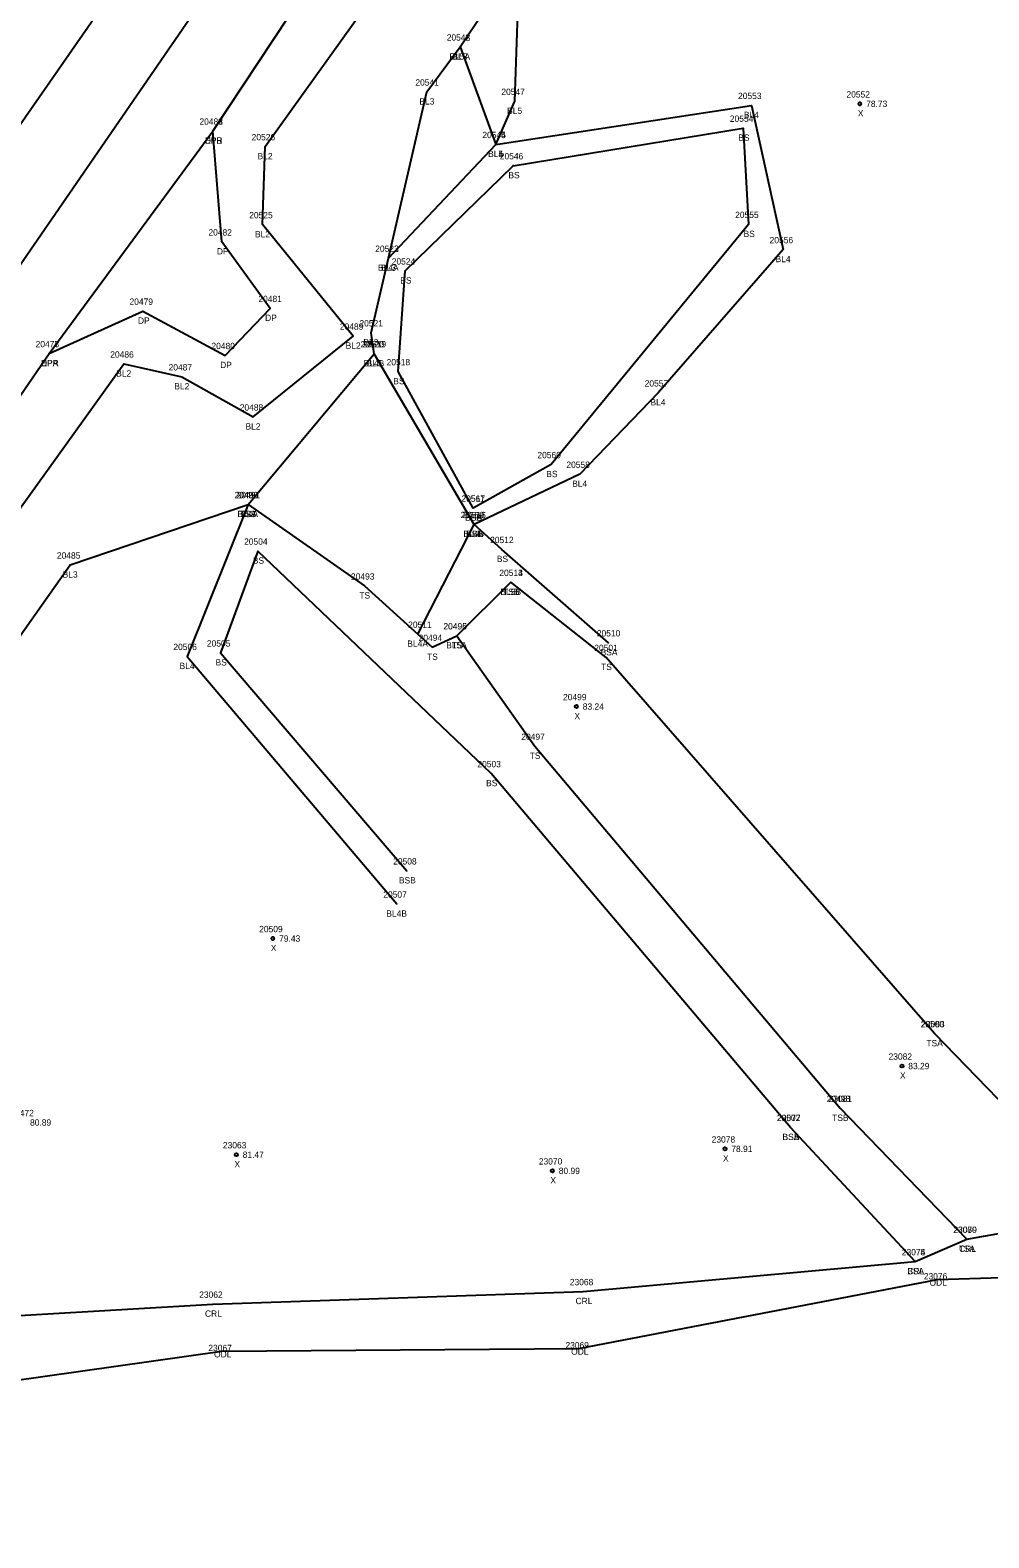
# Model space of a CAD drawing. Extents: x 2266664 to 2272385, y 716533 to 724777.
# Drawn here: x 2267788 to 2267939.8, y 717913.4 to 718152.1 of the extents above; entities that cross this region are included whole.
import ezdxf

# ---------------------------------------------------------------- set-up
doc = ezdxf.new("R2010")
doc.units = 0
for name, color, linetype in [('RD_DTM_BkLn1', 7, 'Continuous'), ('RD_DTM_BkLn2', 7, 'Continuous'), ('RD_EX_Driveway', 7, 'Continuous'), ('RD_EX_Driveway_txCode', 7, 'Continuous'), ('RD_EX_H2O', 7, 'Continuous'), ('RD_EX_H2O_txCode', 7, 'Continuous'), ('RD_EX_Road', 7, 'Continuous'), ('RD_EX_Road_txCode', 7, 'Continuous'), ('RD_Sketch8', 7, 'Continuous'), ('RD_SMD_Locator', 7, 'Continuous'), ('RD_SMD_Misc', 7, 'Continuous')]:
    doc.layers.add(name, color=color, linetype=linetype)

msp = doc.modelspace()

# ---------------------------------------------------------------- linework, layer by layer
at = {"layer": 'RD_DTM_BkLn1'}
msp.add_line((2267855.58, 718056.22), (2267864.15, 718064.68), dxfattribs=at)
for points in [[(2267710.19, 717938.44), (2267719.21, 717959.32), (2267751.93, 718007.38), (2267794.35, 718067.43), (2267822.53, 718077), (2267842.49, 718100.88), (2267841.99, 718104.19), (2267844.77, 718116), (2267850.84, 718142.33), (2267856.09, 718149.45), (2267873.81, 718175.89), (2267927.8, 718259.2), (2267986.43, 718342), (2268046.41, 718424.35), (2268102.94, 718500.87), (2268161.82, 718580.38), (2268222.22, 718658.4), (2268281.14, 718746.18), (2268334.54, 718833.88), (2268359.81, 718873.87), (2268370.29, 718889.66)], [(2267681.84, 717933.24), (2267690.2, 717937.53), (2267742.34, 718015.1), (2267802.82, 718099.26), (2267812.04, 718097.22), (2267823.3, 718090.87), (2267839.17, 718103.67), (2267824.81, 718121.31), (2267825.23, 718133.67), (2267861.61, 718184.44), (2267917.63, 718266.48), (2267975.71, 718350.02), (2268032.51, 718434.82), (2268088.99, 718510.9), (2268143.16, 718593.8), (2268201.81, 718676.06), (2268262.51, 718760.02), (2268318.82, 718844.76)], [(2267667.75, 717943.29), (2267725.37, 718027.06), (2267785.81, 718114.13), (2267843.43, 718197.83), (2267898.55, 718278.61), (2267956.82, 718362.94), (2268015.2, 718447.7), (2268070.98, 718528.34), (2268095.42, 718564.42)], [(2267856.09, 718149.45), (2267861.74, 718134.01), (2267864.75, 718140.85), (2267865.25, 718154.8), (2267873.81, 718175.89)], [(2267844.77, 718116), (2267861.74, 718134.01), (2267902.24, 718140.2), (2267907.27, 718117.37), (2267887.45, 718094.68), (2267875.05, 718081.8), (2267858.3, 718073.84)], [(2267849.42, 718056.47), (2267858.3, 718073.84), (2267842.49, 718100.88)], [(2267822.53, 718077), (2267812.86, 718052.95), (2267846.09, 718013.75)]]:
    msp.add_lwpolyline(points, dxfattribs=at)
at = {"layer": 'RD_DTM_BkLn2'}
for p, q in [((2267936.35, 717960.67), (2267916.29, 717981.41)), ((2267928.18, 717957.12), (2267908.42, 717978.37))]:
    msp.add_line(p, q, dxfattribs=at)
for points in [[(2267858.16, 718076.43), (2267846.29, 718098.04), (2267847.39, 718113.99), (2267864.52, 718130.65), (2267900.93, 718136.59), (2267901.78, 718121.36), (2267870.52, 718083.33), (2267858.16, 718076.43)], [(2267822.53, 718077), (2267840.93, 718064.11), (2267851.65, 718054.4), (2267855.58, 718056.22), (2267867.91, 718038.73), (2267916.29, 717981.41)], [(2267879.62, 718055.11), (2267862.69, 718069.89), (2267858.3, 718073.84)], [(2267908.42, 717978.37), (2267860.99, 718034.4), (2267824.04, 718069.63), (2267818.14, 718053.51), (2267847.65, 718019)], [(2267931.24, 717993.22), (2267879.22, 718052.79), (2267864.15, 718064.68)], [(2267931.24, 717993.22), (2267949.53, 717974.35), (2267969.68, 717972.64), (2267983.72, 717971.75), (2267996.02, 717960.08)]]:
    msp.add_lwpolyline(points, dxfattribs=at)
at = {"layer": 'RD_EX_Driveway'}
msp.add_lwpolyline([(2267790.98, 718100.9), (2267805.85, 718107.62), (2267818.87, 718100.6), (2267825.99, 718108.06), (2267818.35, 718118.59), (2267816.93, 718136.13)], dxfattribs=at)
at = {"layer": 'RD_EX_H2O'}
for points in [[(2267648.67, 717950.99), (2267680, 717930.6), (2267687.12, 717930.39), (2267710.19, 717938.44), (2267744.82, 717946.17), (2267816.91, 717950.39), (2267875.61, 717952.39), (2267928.18, 717957.12), (2267936.35, 717960.67), (2267968.01, 717966.35), (2267984.51, 717962.62), (2267996.02, 717960.08)], [(2267642.67, 717945.91), (2267685.11, 717915.38), (2267739.97, 717931.88), (2267818.36, 717942.95), (2267874.92, 717943.38), (2267931.69, 717954.3), (2267982.65, 717955.87), (2268023.68, 717902.48), (2268035.83, 717858.7), (2268110.12, 717741.99)]]:
    msp.add_lwpolyline(points, dxfattribs=at)
at = {"layer": 'RD_EX_Road'}
for points in [[(2267656.38, 717951.92), (2267658.27, 717950.95), (2267664.43, 717960.69), (2267715.64, 718033.91), (2267761.28, 718100.58), (2267786.41, 718137.16), (2267833.26, 718204.57), (2267888.72, 718285.14), (2267947.43, 718370.13), (2268005.49, 718454.77), (2268062.35, 718536.98), (2268085.26, 718570.22), (2268085.68, 718570.9), (2268114.38, 718613.2), (2268130.13, 718635.29), (2268171.46, 718695.89), (2268186.85, 718718.09), (2268231.02, 718782.78), (2268287.66, 718866.23)], [(2267679.35, 717936.13), (2267677.75, 717937.24), (2267696.23, 717963.72), (2267735.24, 718019.64), (2267790.98, 718100.9), (2267816.93, 718136.13), (2267852.97, 718190.65), (2267908.9, 718272.41), (2267966.54, 718356.05), (2268024.65, 718440.27), (2268080.39, 718521.38), (2268105.01, 718557.4)]]:
    msp.add_lwpolyline(points, dxfattribs=at)
at = {"layer": 'RD_SMD_Locator'}
for centre, radius in [((2267856.09, 718149.45), 0.001), ((2267856.09, 718149.45), 0.001), ((2267850.84, 718142.33), 0.001), ((2267864.75, 718140.85), 0.001), ((2267902.24, 718140.2), 0.001), ((2267919.41, 718140.44), 0.25), ((2267900.93, 718136.59), 0.001), ((2267816.93, 718136.13), 0.001), ((2267816.93, 718136.13), 0.001), ((2267861.74, 718134.01), 0.001), ((2267861.74, 718134.01), 0.001), ((2267825.23, 718133.67), 0.001), ((2267864.52, 718130.65), 0.001), ((2267824.81, 718121.31), 0.001), ((2267901.78, 718121.36), 0.001), ((2267818.35, 718118.59), 0.001), ((2267907.27, 718117.37), 0.001), ((2267844.77, 718116), 0.001), ((2267844.77, 718116), 0.001), ((2267847.39, 718113.99), 0.001), ((2267825.99, 718108.06), 0.001), ((2267805.85, 718107.62), 0.001), ((2267839.17, 718103.67), 0.001), ((2267841.99, 718104.19), 0.001), ((2267790.98, 718100.9), 0.001), ((2267790.98, 718100.9), 0.001), ((2267818.87, 718100.6), 0.001), ((2267842.49, 718100.88), 0.001), ((2267842.49, 718100.88), 0.001), ((2267802.82, 718099.26), 0.001), ((2267812.04, 718097.22), 0.001), ((2267846.29, 718098.04), 0.001), ((2267887.45, 718094.68), 0.001), ((2267823.3, 718090.87), 0.001), ((2267870.52, 718083.33), 0.001), ((2267875.05, 718081.8), 0.001), ((2267822.53, 718077), 0.001), ((2267822.53, 718077), 0.001), ((2267822.53, 718077), 0.001), ((2267858.16, 718076.43), 0.001), ((2267858.16, 718076.43), 0.001), ((2267858.3, 718073.84), 0.001), ((2267858.3, 718073.84), 0.001), ((2267858.3, 718073.84), 0.001), ((2267824.04, 718069.63), 0.001), ((2267862.69, 718069.89), 0.001), ((2267794.35, 718067.43), 0.001), ((2267840.93, 718064.11), 0.001), ((2267864.15, 718064.68), 0.001), ((2267864.15, 718064.68), 0.001), ((2267849.42, 718056.47), 0.001), ((2267855.58, 718056.22), 0.001), ((2267855.58, 718056.22), 0.001), ((2267812.86, 718052.95), 0.001), ((2267818.14, 718053.51), 0.001), ((2267851.65, 718054.4), 0.001), ((2267879.22, 718052.79), 0.001), ((2267879.62, 718055.11), 0.001), ((2267874.52, 718045.01), 0.25), ((2267867.91, 718038.73), 0.001), ((2267860.99, 718034.4), 0.001), ((2267847.65, 718019), 0.001), ((2267846.09, 718013.75), 0.001), ((2267826.43, 718008.28), 0.25), ((2267931.24, 717993.22), 0.001), ((2267931.24, 717993.22), 0.001), ((2267926.08, 717988.09), 0.25), ((2267916.29, 717981.41), 0.001), ((2267916.29, 717981.41), 0.001), ((2267908.42, 717978.37), 0.001), ((2267908.42, 717978.37), 0.001), ((2267820.66, 717974.05), 0.25), ((2267898.05, 717974.97), 0.25), ((2267870.72, 717971.5), 0.25), ((2267936.35, 717960.67), 0.001), ((2267936.35, 717960.67), 0.001), ((2267928.18, 717957.12), 0.001), ((2267928.18, 717957.12), 0.001), ((2267931.69, 717954.3), 0.001), ((2267816.91, 717950.39), 0.001), ((2267875.61, 717952.39), 0.001), ((2267818.36, 717942.95), 0.001), ((2267874.92, 717943.38), 0.001)]:
    msp.add_circle(centre, radius, dxfattribs=at)

# ---------------------------------------------------------------- texts
at = {"layer": 'RD_EX_Driveway_txCode'}
for s, p in [('20483', (2267814.81, 718137.13)), ('DPB', (2267815.67, 718134.13)), ('20482', (2267816.23, 718119.59)), ('DP', (2267817.57, 718116.59)), ('20481', (2267824.15, 718109.06)), ('20479', (2267803.73, 718108.62)), ('DP', (2267805.07, 718105.62)), ('DP', (2267825.21, 718106.06)), ('20478', (2267788.86, 718101.9)), ('20480', (2267816.71, 718101.6)), ('DPA', (2267789.71, 718098.9)), ('DP', (2267818.09, 718098.6))]:
    msp.add_text(s, height=1, dxfattribs=at).set_placement(p)
at = {"layer": 'RD_EX_H2O_txCode'}
for s, p in [('23079', (2267934.24, 717961.67)), ('CRL', (2267935.13, 717958.67)), ('23074', (2267926.06, 717958.12)), ('CRL', (2267926.95, 717955.12)), ('23076', (2267929.54, 717954.3)), ('23068', (2267873.47, 717953.39)), ('ODL', (2267930.44, 717953.3)), ('23062', (2267814.77, 717951.39)), ('CRL', (2267874.38, 717950.39)), ('CRL', (2267815.68, 717948.39)), ('23067', (2267816.22, 717942.95)), ('ODL', (2267817.12, 717941.95)), ('23069', (2267872.78, 717943.38)), ('ODL', (2267873.68, 717942.38))]:
    msp.add_text(s, height=1, dxfattribs=at).set_placement(p)
at = {"layer": 'RD_EX_Road_txCode'}
for s, p in [('20484', (2267814.81, 718137.13)), ('EPR', (2267815.7, 718134.13)), ('20477', (2267788.86, 718101.9)), ('EPR', (2267789.75, 718098.9))]:
    msp.add_text(s, height=1, dxfattribs=at).set_placement(p)
at = {"layer": 'RD_Sketch8'}
for s, p in [('20552', (2267917.29, 718141.44)), ('X', (2267919.09, 718138.44)), ('78.73', (2267920.41, 718139.94)), ('20499', (2267872.4, 718046.01)), ('X', (2267874.2, 718043.01)), ('83.24', (2267875.52, 718044.51)), ('20509', (2267824.27, 718009.28)), ('79.43', (2267827.43, 718007.78)), ('X', (2267826.11, 718006.28)), ('23082', (2267923.96, 717989.09)), ('83.29', (2267927.08, 717987.59)), ('X', (2267925.76, 717986.09)), ('20472', (2267784.86, 717980.15)), ('80.89', (2267787.98, 717978.65)), ('23078', (2267895.94, 717975.97)), ('23063', (2267818.52, 717975.05)), ('81.47', (2267821.66, 717973.55)), ('X', (2267897.74, 717972.97)), ('78.91', (2267899.05, 717974.47)), ('X', (2267820.35, 717972.05)), ('23070', (2267868.56, 717972.5)), ('80.99', (2267871.72, 717971)), ('X', (2267870.4, 717969.5))]:
    msp.add_text(s, height=1, dxfattribs=at).set_placement(p)
at = {"layer": 'RD_SMD_Misc'}
for s, p in [('20542', (2267853.98, 718150.45)), ('20543', (2267853.98, 718150.45)), ('BL5A', (2267854.4, 718147.45)), ('BL3', (2267854.89, 718147.45)), ('20541', (2267849.01, 718143.33)), ('BL3', (2267849.64, 718140.33)), ('20547', (2267862.63, 718141.85)), ('20553', (2267900.12, 718141.2)), ('BL5', (2267863.54, 718138.85)), ('BL4', (2267901.04, 718138.2)), ('20554', (2267898.82, 718137.59)), ('20526', (2267823.08, 718134.67)), ('20544', (2267859.62, 718135.01)), ('20545', (2267859.62, 718135.01)), ('BS', (2267900.16, 718134.59)), ('BL2', (2267824.02, 718131.67)), ('BL5', (2267860.53, 718132.01)), ('BL4', (2267860.53, 718132.01)), ('20546', (2267862.38, 718131.65)), ('BS', (2267863.74, 718128.65)), ('20525', (2267822.69, 718122.31)), ('20555', (2267899.66, 718122.36)), ('BL2', (2267823.61, 718119.31)), ('BS', (2267901, 718119.36)), ('20522', (2267842.65, 718117)), ('20523', (2267842.65, 718117)), ('20556', (2267905.12, 718118.37)), ('BL4A', (2267843.08, 718114)), ('BL3', (2267843.57, 718114)), ('20524', (2267845.27, 718114.99)), ('BL4', (2267906.06, 718115.37)), ('BS', (2267846.61, 718111.99)), ('20489', (2267837.05, 718104.67)), ('20521', (2267840.15, 718105.19)), ('20520', (2267840.33, 718101.88)), ('20519', (2267840.65, 718101.88)), ('BL3', (2267840.78, 718102.19)), ('20486', (2267800.68, 718100.26)), ('BL2', (2267837.97, 718101.67)), ('BL2', (2267801.62, 718097.26)), ('20487', (2267809.92, 718098.22)), ('BL4B', (2267840.81, 718098.88)), ('BL3', (2267841.28, 718098.88)), ('20518', (2267844.46, 718099.04)), ('BL2', (2267810.83, 718095.22)), ('BS', (2267845.51, 718096.04)), ('20557', (2267885.33, 718095.68)), ('BL4', (2267886.25, 718092.68)), ('20488', (2267821.19, 718091.87)), ('BL2', (2267822.1, 718088.87)), ('20560', (2267868.34, 718084.33)), ('20558', (2267872.93, 718082.8)), ('BS', (2267869.74, 718081.33)), ('20490', (2267820.37, 718078)), ('20492', (2267820.41, 718078)), ('20491', (2267820.69, 718078)), ('BL4', (2267873.84, 718079.8)), ('20561', (2267856.3, 718077.43)), ('20517', (2267856.32, 718077.43)), ('BL4A', (2267820.83, 718075)), ('TSA', (2267821.24, 718075)), ('BL3', (2267821.32, 718075)), ('20559', (2267856.18, 718074.84)), ('20516', (2267856.44, 718074.84)), ('20515', (2267856.46, 718074.84)), ('BSA', (2267856.89, 718074.43)), ('BSB', (2267856.9, 718074.43)), ('BL4B', (2267856.62, 718071.84)), ('BSB', (2267857.05, 718071.84)), ('BL4', (2267857.09, 718071.84)), ('20512', (2267860.85, 718070.89)), ('20504', (2267821.88, 718070.63)), ('20485', (2267792.23, 718068.43)), ('BS', (2267823.26, 718067.63)), ('BS', (2267861.91, 718067.89)), ('BL3', (2267793.14, 718065.43)), ('20493', (2267838.81, 718065.11)), ('20513', (2267862.31, 718065.68)), ('20514', (2267862.31, 718065.68)), ('TS', (2267840.13, 718062.11)), ('BL5B', (2267862.47, 718062.68)), ('TSB', (2267862.88, 718062.68)), ('20511', (2267847.87, 718057.47)), ('20496', (2267853.44, 718057.22)), ('20495', (2267853.46, 718057.22)), ('20505', (2267815.99, 718054.51)), ('BL4A', (2267847.73, 718054.47)), ('20494', (2267849.53, 718055.4)), ('BL5A', (2267853.89, 718054.22)), ('TS', (2267854.79, 718054.22)), ('20510', (2267877.75, 718056.11)), ('20506', (2267810.68, 718053.95)), ('TS', (2267850.86, 718052.4)), ('20501', (2267877.35, 718053.79)), ('BSA', (2267878.35, 718053.11)), ('BL4', (2267811.66, 718050.95)), ('BS', (2267817.36, 718051.51)), ('TS', (2267878.42, 718050.79)), ('20497', (2267865.79, 718039.73)), ('20503', (2267858.83, 718035.4)), ('TS', (2267867.11, 718036.73)), ('BS', (2267860.21, 718032.4)), ('20508', (2267845.49, 718020)), ('BSB', (2267846.4, 718017)), ('20507', (2267843.93, 718014.75)), ('BL4B', (2267844.41, 718011.75)), ('20500', (2267929.04, 717994.22)), ('23083', (2267929.12, 717994.22)), ('TSA', (2267929.95, 717991.22)), ('TSA', (2267929.95, 717991.22)), ('20498', (2267914.18, 717982.41)), ('23081', (2267914.46, 717982.41)), ('20502', (2267906.26, 717979.37)), ('23077', (2267906.3, 717979.37)), ('TSB', (2267915.03, 717979.41)), ('TSB', (2267915.03, 717979.41)), ('BSA', (2267907.15, 717976.37)), ('BSB', (2267907.17, 717976.37)), ('23080', (2267934.2, 717961.67)), ('TSA', (2267935.07, 717958.67)), ('23075', (2267926.06, 717958.12)), ('BSA', (2267926.91, 717955.12))]:
    msp.add_text(s, height=1, dxfattribs=at).set_placement(p)

doc.saveas('drawing.dxf')
